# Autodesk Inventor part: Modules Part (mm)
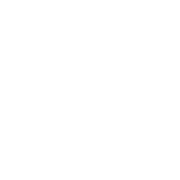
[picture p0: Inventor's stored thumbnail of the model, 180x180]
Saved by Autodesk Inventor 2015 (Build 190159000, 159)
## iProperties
Created: 2014-08
Part Number: Modules Part (mm)
Material: Generic
Document SubType Name: Modeling
Designer: Wally
Density: 1 g/cm^3
Appearance: Default
Author: Wally
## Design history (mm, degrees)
node "Sketch1"
